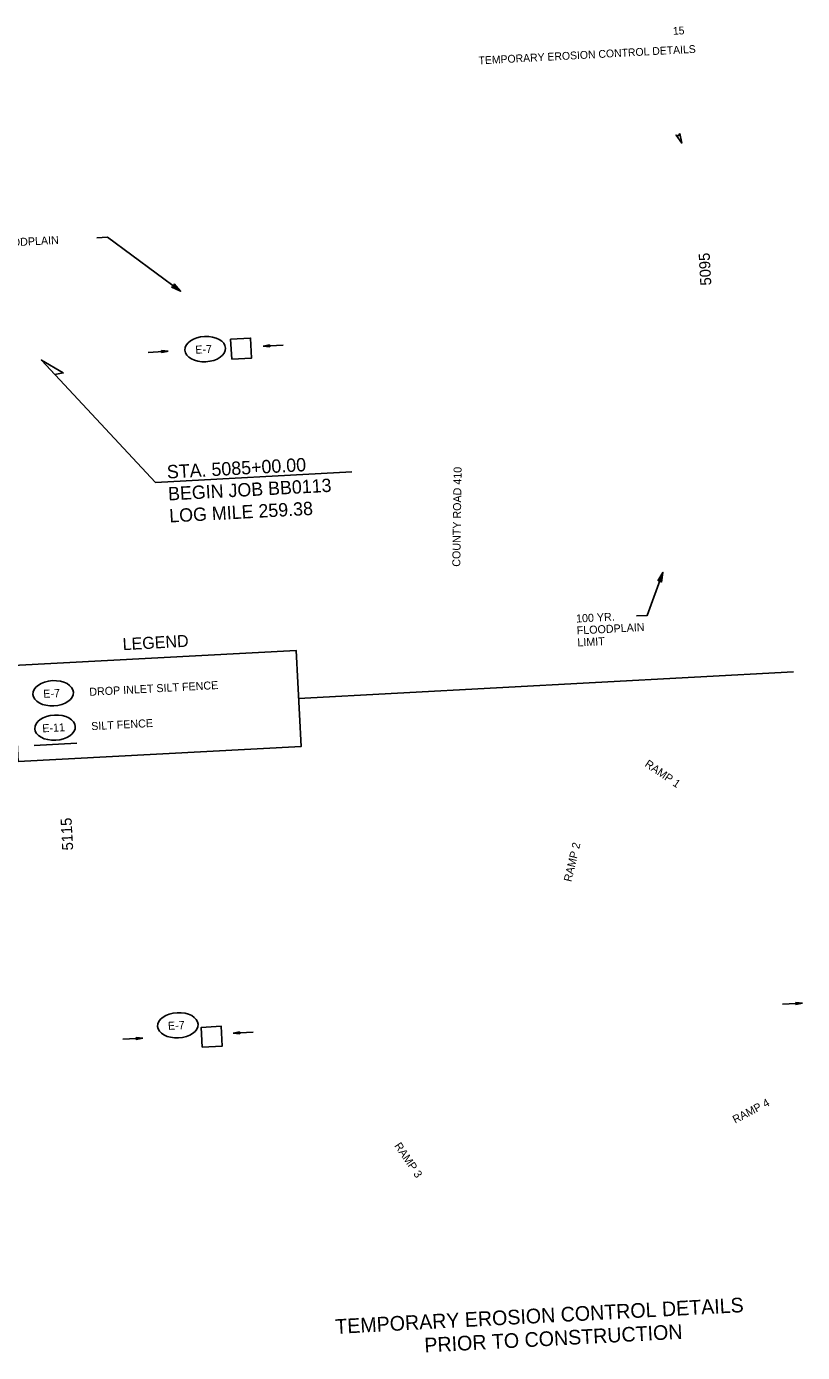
# Model space of a CAD drawing. Extents: x 251072 to 254282, y 223355 to 226019.
# Drawn here: x 253119 to 254282, y 223422 to 225410 of the extents above; entities that cross this region are included whole.
import ezdxf

# ---------------------------------------------------------------- set-up
doc = ezdxf.new("R2010")
doc.units = 0
for name, color, linetype in [('24X36', 7, 'Continuous'), ('DRAINAGE', 7, 'Continuous'), ('Level 1', 7, 'Continuous'), ('Level 15', 7, 'Continuous'), ('Level 2', 7, 'Continuous'), ('Level 24', 7, 'Continuous'), ('Level 30', 7, 'Continuous'), ('Level 58', 7, 'Continuous'), ('Level 59', 7, 'Continuous'), ('R_Water Annot', 7, 'Continuous'), ('STATIONING1', 7, 'Continuous')]:
    doc.layers.add(name, color=color, linetype=linetype)

msp = doc.modelspace()

# ---------------------------------------------------------------- linework, layer by layer
at = {"layer": '24X36'}
msp.add_line((253130.1, 224332.4), (253194, 224335.9), dxfattribs=at)
for points in [[(253426.3, 224911.7), (253456.2, 224913.3), (253454.6, 224943.1), (253424.7, 224941.5)], [(253382.3, 223879.7), (253412.2, 223881.3), (253410.6, 223911.1), (253380.7, 223909.5)]]:
    msp.add_lwpolyline(points, close=True, dxfattribs=at)
at = {"layer": 'DRAINAGE'}
for p, q in [((253321.2, 224924.4), (253331.2, 224923.4)), ((253321.3, 224921.4), (253321.2, 224924.4)), ((253321.2, 224924.1), (253329.6, 224923.3)), ((253321.2, 224923.9), (253327.9, 224923.2)), ((253321.2, 224923.6), (253326.2, 224923.1)), ((253321.2, 224923.4), (253324.5, 224923)), ((253321.2, 224923.1), (253322.8, 224922.9)), ((253321.3, 224921.4), (253331.2, 224923.4)), ((253321.3, 224921.6), (253329.6, 224923.3)), ((253321.3, 224921.9), (253327.9, 224923.2)), ((253321.3, 224922.1), (253326.2, 224923.1)), ((253321.3, 224922.4), (253324.5, 224923)), ((253321.3, 224922.6), (253322.8, 224922.9)), ((253483.2, 224933.1), (253473.3, 224931)), ((253483.4, 224930.1), (253473.3, 224931)), ((253483.2, 224932.8), (253475, 224931.1)), ((253483.4, 224930.3), (253475, 224931.1)), ((253483.2, 224932.6), (253476.7, 224931.2)), ((253483.4, 224930.6), (253476.7, 224931.2)), ((253483.3, 224932.3), (253478.4, 224931.3)), ((253483.3, 224930.8), (253478.4, 224931.3)), ((253483.3, 224932.1), (253480.1, 224931.4)), ((253483.3, 224931.1), (253480.1, 224931.4)), ((253483.3, 224931.8), (253481.7, 224931.5)), ((253483.3, 224931.3), (253481.7, 224931.5)), ((253483.4, 224930.1), (253483.2, 224933.1)), ((254271.9, 223946.8), (254282, 223945.8)), ((254272.1, 223943.8), (254271.9, 223946.8)), ((254271.9, 223946.5), (254280.3, 223945.7)), ((254272, 223946.3), (254278.6, 223945.6)), ((254272, 223946), (254276.9, 223945.6)), ((254272, 223945.8), (254275.3, 223945.5)), ((254272, 223944.6), (254276.9, 223945.6)), ((254272, 223944.8), (254275.3, 223945.5)), ((254272, 223945.5), (254273.6, 223945.4)), ((254272, 223945.1), (254273.6, 223945.4)), ((254272.1, 223943.8), (254282, 223945.8)), ((254272.1, 223944), (254280.3, 223945.7)), ((254272.1, 223944.3), (254278.6, 223945.6)), ((253282.9, 223894.3), (253293, 223893.3)), ((253283, 223891.3), (253282.9, 223894.3)), ((253282.9, 223894), (253291.3, 223893.2)), ((253282.9, 223893.8), (253289.6, 223893.1)), ((253282.9, 223893.5), (253287.9, 223893)), ((253282.9, 223893.3), (253286.2, 223893)), ((253283, 223891.3), (253293, 223893.3)), ((253283, 223891.5), (253291.3, 223893.2)), ((253283, 223891.8), (253289.6, 223893.1)), ((253283, 223892.3), (253286.2, 223893)), ((253283, 223892), (253287.9, 223893)), ((253283, 223893), (253284.5, 223892.9)), ((253283, 223892.6), (253284.5, 223892.9)), ((253438.2, 223902.6), (253428.3, 223900.6)), ((253438.4, 223899.6), (253428.3, 223900.6)), ((253438.2, 223902.4), (253430, 223900.7)), ((253438.4, 223899.9), (253430, 223900.7)), ((253438.2, 223902.1), (253431.7, 223900.8)), ((253438.4, 223900.1), (253431.7, 223900.8)), ((253438.3, 223901.9), (253433.4, 223900.9)), ((253438.3, 223900.4), (253433.4, 223900.9)), ((253438.3, 223901.6), (253435.1, 223901)), ((253438.3, 223900.6), (253435.1, 223901)), ((253438.3, 223901.4), (253436.7, 223901)), ((253438.3, 223900.9), (253436.7, 223901)), ((253438.4, 223899.6), (253438.2, 223902.6))]:
    msp.add_line(p, q, dxfattribs=at)
at = {"layer": 'Level 1'}
msp.add_line((253526.7, 224402.8), (254268.3, 224442.6), dxfattribs=at)
msp.add_lwpolyline([(253098.7, 224452), (253522.9, 224474.7), (253530.6, 224330.9), (253106.4, 224308.2)], close=True, dxfattribs=at)
at = {"layer": 'Level 24'}
for points in [[(253224, 225093.5), (253240, 225094.4), (253349.7, 225013.3)], [(253312.1, 224726.8), (253141.1, 224910.2)], [(253312.1, 224726.8), (253606.2, 224742.6)], [(254033.3, 224526.4), (254049.3, 224527.2), (254072.9, 224591.8)]]:
    msp.add_lwpolyline(points, dxfattribs=at)
at = {"layer": 'Level 30'}
for centre in [(253386.7, 224926.6), (253158.7, 224410.5), (253161.5, 224359), (253345.6, 223912.6)]:
    msp.add_ellipse(centre, major_axis=(30.4, 1.6), ratio=0.622507, dxfattribs=at)
at = {"layer": 'Level 58'}
for points in [[(254097.9, 225250.1), (254101.1, 225235.7), (254092.5, 225247.6), (254096.2, 225246.7)], [(253340, 225024.4), (253349.7, 225013.3), (253336.4, 225019.6), (253340.1, 225020.5)], [(254065.1, 224579.3), (254072.9, 224591.8), (254070.7, 224577.2), (254068.7, 224580.5)]]:
    msp.add_lwpolyline(points, close=True, dxfattribs=at)
at = {"layer": 'Level 59'}
msp.add_lwpolyline([(253161.2, 224888.7), (253141.1, 224910.2), (253173.7, 224890.9)], close=True, dxfattribs=at)
at = {"layer": 'STATIONING1'}
for p, q in [((253301.3, 224921.8), (253331.2, 224923.4)), ((253321.2, 224924.4), (253331.2, 224923.4)), ((253321.3, 224921.4), (253321.2, 224924.4)), ((253321.2, 224924.1), (253329.6, 224923.3)), ((253321.2, 224923.9), (253327.9, 224923.2)), ((253321.2, 224923.6), (253326.2, 224923.1)), ((253321.2, 224923.4), (253324.5, 224923)), ((253321.2, 224923.1), (253322.8, 224922.9)), ((253321.3, 224921.4), (253331.2, 224923.4)), ((253321.3, 224921.6), (253329.6, 224923.3)), ((253321.3, 224921.9), (253327.9, 224923.2)), ((253321.3, 224922.1), (253326.2, 224923.1)), ((253321.3, 224922.4), (253324.5, 224923)), ((253321.3, 224922.6), (253322.8, 224922.9)), ((253483.2, 224933.1), (253473.3, 224931)), ((253503.3, 224932.7), (253473.3, 224931)), ((253483.4, 224930.1), (253473.3, 224931)), ((253483.2, 224932.8), (253475, 224931.1)), ((253483.4, 224930.3), (253475, 224931.1)), ((253483.2, 224932.6), (253476.7, 224931.2)), ((253483.4, 224930.6), (253476.7, 224931.2)), ((253483.3, 224932.3), (253478.4, 224931.3)), ((253483.3, 224930.8), (253478.4, 224931.3)), ((253483.3, 224932.1), (253480.1, 224931.4)), ((253483.3, 224931.1), (253480.1, 224931.4)), ((253483.3, 224931.8), (253481.7, 224931.5)), ((253483.3, 224931.3), (253481.7, 224931.5)), ((253483.4, 224930.1), (253483.2, 224933.1)), ((254252, 223944.3), (254282, 223945.8)), ((254271.9, 223946.8), (254282, 223945.8)), ((254272.1, 223943.8), (254271.9, 223946.8)), ((254271.9, 223946.5), (254280.3, 223945.7)), ((254272, 223946.3), (254278.6, 223945.6)), ((254272, 223946), (254276.9, 223945.6)), ((254272, 223945.8), (254275.3, 223945.5)), ((254272, 223944.6), (254276.9, 223945.6)), ((254272, 223944.8), (254275.3, 223945.5)), ((254272, 223945.5), (254273.6, 223945.4)), ((254272, 223945.1), (254273.6, 223945.4)), ((254272.1, 223943.8), (254282, 223945.8)), ((254272.1, 223944), (254280.3, 223945.7)), ((254272.1, 223944.3), (254278.6, 223945.6)), ((253263, 223891.8), (253293, 223893.3)), ((253282.9, 223894.3), (253293, 223893.3)), ((253283, 223891.3), (253282.9, 223894.3)), ((253282.9, 223894), (253291.3, 223893.2)), ((253282.9, 223893.8), (253289.6, 223893.1)), ((253282.9, 223893.5), (253287.9, 223893)), ((253282.9, 223893.3), (253286.2, 223893)), ((253283, 223891.3), (253293, 223893.3)), ((253283, 223891.5), (253291.3, 223893.2)), ((253283, 223891.8), (253289.6, 223893.1)), ((253283, 223892.3), (253286.2, 223893)), ((253283, 223892), (253287.9, 223893)), ((253283, 223893), (253284.5, 223892.9)), ((253283, 223892.6), (253284.5, 223892.9)), ((253438.2, 223902.6), (253428.3, 223900.6)), ((253458.3, 223902.3), (253428.3, 223900.6)), ((253438.4, 223899.6), (253428.3, 223900.6)), ((253438.2, 223902.4), (253430, 223900.7)), ((253438.4, 223899.9), (253430, 223900.7)), ((253438.2, 223902.1), (253431.7, 223900.8)), ((253438.4, 223900.1), (253431.7, 223900.8)), ((253438.3, 223901.9), (253433.4, 223900.9)), ((253438.3, 223900.4), (253433.4, 223900.9)), ((253438.3, 223901.6), (253435.1, 223901)), ((253438.3, 223900.6), (253435.1, 223901)), ((253438.3, 223901.4), (253436.7, 223901)), ((253438.3, 223900.9), (253436.7, 223901)), ((253438.4, 223899.6), (253438.2, 223902.6))]:
    msp.add_line(p, q, dxfattribs=at)

# ---------------------------------------------------------------- texts
at = {"layer": 'Level 1'}
for s, height, p in [('15', 11.72, (254088, 225397.9)), ('TEMPORARY EROSION CONTROL DETAILS', 11.7, (253796.7, 225353.6))]:
    msp.add_text(s, height=height, rotation=3.0666, dxfattribs=at).set_placement(p)
at = {"layer": 'Level 15'}
msp.add_text('5095', height=16.5, rotation=93.0667, dxfattribs=at).set_placement((254145.4, 225022.5))
at = {"layer": 'Level 2'}
for s, p in [('TEMPORARY EROSION CONTROL DETAILS', (253582.2, 223449.7)), ('PRIOR TO CONSTRUCTION', (253715.8, 223421.8))]:
    msp.add_text(s, height=22, rotation=3.0666, dxfattribs=at).set_placement(p)
at = {"layer": 'Level 24'}
for s, height, rotation, p in [('100 YR. FLOODPLAIN', 12, 3.0666, (253003.5, 225075.7)), ('STA. 5085+00.00', 20, 3.0667, (253329.7, 224732.5)), ('COUNTY ROAD 410', 12, 89.2169, (253769, 224600.2)), ('BEGIN JOB BB0113', 20, 3.0667, (253331.5, 224699.6)), ('LOG MILE 259.38', 20, 3.0667, (253333.3, 224666.6)), ('100 YR.', 12, 3.0666, (253942.9, 224516.5)), ('FLOODPLAIN', 12, 3.0666, (253943.9, 224498.6)), ('LIMIT', 12, 3.0666, (253944.9, 224480.6)), ('RAMP 1', 12, 325.5666, (254044.5, 224301.8)), ('RAMP 2', 12, 76.6656, (253935.5, 224127)), ('RAMP 4', 12, 27.7427, (254181.1, 223765)), ('RAMP 3', 12, 304.0723, (253669.6, 223731.9))]:
    msp.add_text(s, height=height, rotation=rotation, dxfattribs=at).set_placement(p)
at = {"layer": 'Level 30'}
for s, height, p in [('E-7', 12, (253372.1, 224919.7)), ('LEGEND', 18, (253263.3, 224475.1)), ('DROP INLET SILT FENCE', 11.997, (253213.2, 224406.6)), ('E-7', 12, (253144.2, 224403.6)), ('E-11', 12, (253142.7, 224351.9)), ('SILT FENCE ', 11.997, (253216, 224355.1)), ('E-7', 12, (253331.1, 223905.7))]:
    msp.add_text(s, height=height, rotation=3.0666, dxfattribs=at).set_placement(p)
at = {"layer": 'R_Water Annot'}
msp.add_text('5115', height=16.5, rotation=93.0667, dxfattribs=at).set_placement((253188.8, 224175.3))

doc.saveas('drawing.dxf')
